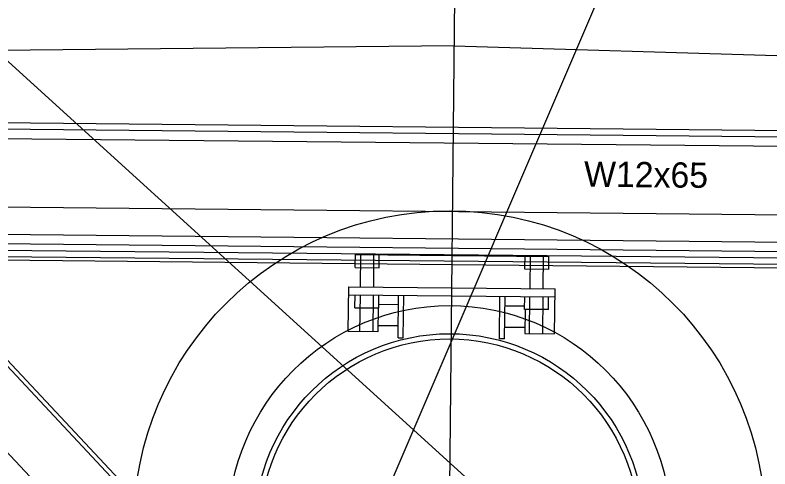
# Model space of a CAD drawing. Extents: x 632312 to 632885, y 378199 to 378534.
# Drawn here: x 632769.45 to 632775.42, y 378352.33 to 378355.92 of the extents above; entities that cross this region are included whole.
import ezdxf

# ---------------------------------------------------------------- set-up
doc = ezdxf.new("R2010")
doc.units = 0
for name, color, linetype in [('B_Boring', 7, 'Continuous'), ('B_Boring Annot', 7, 'Continuous'), ('R_Border', 7, 'Continuous'), ('R_Proposed Const Limits Cut', 7, 'Continuous'), ('R_Road Edge of Shoulder', 7, 'Continuous'), ('SHT_Dimensions', 7, 'Continuous'), ('USACE_Easement', 7, 'Continuous')]:
    doc.layers.add(name, color=color, linetype=linetype)

msp = doc.modelspace()

# ---------------------------------------------------------------- linework, layer by layer
at = {"layer": 'B_Boring'}
for p, q in [((632778.4148, 378354.9246), (632767.4153, 378355.034)), ((632778.4153, 378354.975), (632767.4158, 378355.0844)), ((632778.4053, 378353.9667), (632767.4058, 378354.0761)), ((632778.4058, 378354.0172), (632767.4063, 378354.1265)), ((632772.1386, 378353.9217), (632772.1397, 378354.029)), ((632773.6714, 378354.0066), (632772.1396, 378354.0218)), ((632772.1793, 378353.7686), (632772.1819, 378354.0286)), ((632772.2841, 378353.7676), (632772.2866, 378354.0276)), ((632772.3278, 378353.9198), (632772.3288, 378354.0272)), ((632768.3634, 378353.9906), (632772.9048, 378353.9454)), ((632773.4812, 378353.9083), (632773.4823, 378354.0157)), ((632773.5219, 378353.7553), (632773.5245, 378354.0153)), ((632773.6267, 378353.7542), (632773.6292, 378354.0142)), ((632773.6704, 378353.9065), (632773.6714, 378354.0138)), ((632772.1386, 378353.9217), (632772.3278, 378353.9198)), ((632772.9048, 378353.9454), (632777.4462, 378353.9002)), ((632773.6704, 378353.9065), (632773.4812, 378353.9083)), ((632772.0832, 378353.4146), (632772.0867, 378353.7695)), ((632772.0867, 378353.7695), (632773.7192, 378353.7533)), ((632773.7157, 378353.3984), (632773.7192, 378353.7533)), ((632772.0861, 378353.7063), (632773.7186, 378353.6901)), ((632772.1354, 378353.6037), (632772.1365, 378353.7058)), ((632772.1757, 378353.4137), (632772.1786, 378353.7054)), ((632772.2805, 378353.4127), (632772.2834, 378353.7044)), ((632772.3246, 378353.6018), (632772.3256, 378353.704)), ((632772.4777, 378353.3666), (632772.481, 378353.7024)), ((632772.5188, 378353.3662), (632772.5221, 378353.702)), ((632773.2792, 378353.3586), (632773.2826, 378353.6944)), ((632773.3203, 378353.3582), (632773.3237, 378353.694)), ((632773.478, 378353.5904), (632773.4791, 378353.6925)), ((632773.5183, 378353.4004), (632773.5212, 378353.6921)), ((632773.6231, 378353.3993), (632773.626, 378353.691)), ((632773.6672, 378353.5885), (632773.6682, 378353.6906)), ((632772.1354, 378353.6037), (632772.3246, 378353.6018)), ((632772.3192, 378353.6019), (632772.3173, 378353.4123)), ((632772.4803, 378353.6275), (632772.3249, 378353.629)), ((632773.3229, 378353.6191), (632773.4783, 378353.6176)), ((632773.6672, 378353.5885), (632773.478, 378353.5904)), ((632773.4834, 378353.5903), (632773.4815, 378353.4007)), ((632772.4786, 378353.4595), (632772.3178, 378353.4611)), ((632773.3212, 378353.4511), (632773.482, 378353.4495)), ((632772.3173, 378353.4123), (632772.0832, 378353.4146)), ((632772.4777, 378353.3666), (632772.5188, 378353.3662)), ((632773.4815, 378353.4007), (632773.7157, 378353.3984)), ((632773.3203, 378353.3582), (632773.2792, 378353.3586))]:
    msp.add_line(p, q, dxfattribs=at)
msp.add_lwpolyline([(632770.3381, 378351.4407), (632768.359, 378353.5494), (632768.7235, 378353.8916), (632770.3453, 378352.1637)], dxfattribs=at)
for radius in [1.5417, 1.5]:
    msp.add_circle((632772.884, 378351.8564), radius, dxfattribs=at)
at = {"layer": 'B_Boring Annot'}
for q in [(632768.9631, 378355.6347), (632776.8793, 378355.556)]:
    msp.add_line((632772.922, 378355.6745), q, dxfattribs=at)
at = {"layer": 'R_Border'}
for radius in [2.5, 1.75]:
    msp.add_circle((632772.8842, 378351.8705), radius, dxfattribs=at)
at = {"layer": 'R_Proposed Const Limits Cut'}
for p, q in [((632778.4141, 378354.85), (632767.4146, 378354.9594)), ((632777.4504, 378354.3169), (632768.3675, 378354.4072)), ((632778.4065, 378354.0917), (632767.4071, 378354.2011)), ((632777.4465, 378353.9263), (632768.3636, 378354.0166)), ((632768.7008, 378353.8702), (632777.3319, 378344.6741))]:
    msp.add_line(p, q, dxfattribs=at)
at = {"layer": 'R_Road Edge of Shoulder'}
msp.add_line((632772.7538, 378338.7619), (632773.0843, 378372.0036), dxfattribs=at)
at = {"layer": 'USACE_Easement'}
for p, q in [((632765.668, 378336.4864), (632777.7733, 378364.6944)), ((632763.7089, 378360.7088), (632793.4152, 378333.7352))]:
    msp.add_line(p, q, dxfattribs=at)

# ---------------------------------------------------------------- texts
at = {"layer": 'SHT_Dimensions'}
msp.add_text('W12x65', height=0.2, rotation=359.43036, dxfattribs=at).set_placement((632773.9484, 378354.5609))

doc.saveas('drawing.dxf')
